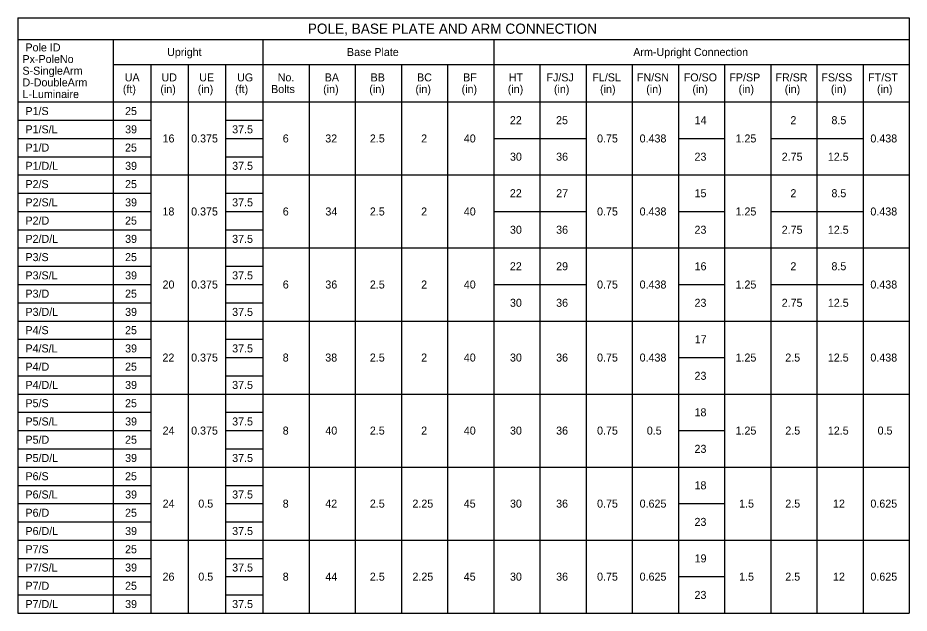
# Model space of a CAD drawing. Extents: x -1.3 to 14.1, y 0 to 9.3.
# Drawn here: x 6.35 to 14.14, y 4.14 to 9.34 of the extents above; entities that cross this region are included whole.
import ezdxf

# ---------------------------------------------------------------- set-up
doc = ezdxf.new("R2010")
doc.units = 0
for name, color, linetype in [('SumBoxBorder_dp', 7, 'Continuous'), ('SumBoxLines_dp', 7, 'Continuous'), ('TextLabel', 7, 'Continuous')]:
    doc.layers.add(name, color=color, linetype=linetype)

msp = doc.modelspace()

# ---------------------------------------------------------------- linework, layer by layer
at = {"layer": 'SumBoxBorder_dp'}
for p, q in [((6.345, 9.3443), (14.1396, 9.3443)), ((6.345, 9.3443), (6.345, 4.1392)), ((14.1396, 9.3443), (14.1396, 4.1392)), ((6.345, 9.1545), (14.1396, 9.1545)), ((6.345, 9.1545), (14.1396, 9.1545)), ((6.345, 4.1392), (14.1396, 4.1392))]:
    msp.add_line(p, q, dxfattribs=at)
at = {"layer": 'SumBoxLines_dp'}
for p, q in [((7.1796, 9.1545), (7.1796, 4.1392)), ((7.1796, 9.1545), (7.1796, 4.1392)), ((8.4887, 9.1545), (8.4887, 4.1392)), ((8.4887, 9.1545), (8.4887, 4.1392)), ((10.5069, 9.1545), (10.5069, 4.1392)), ((10.5069, 9.1545), (10.5069, 4.1392)), ((7.1796, 8.9363), (14.1396, 8.9363)), ((7.1796, 8.9363), (14.1396, 8.9363)), ((7.5069, 8.9363), (7.5069, 4.1392)), ((7.5069, 8.9363), (7.5069, 4.1392)), ((7.8341, 8.9363), (7.8341, 4.1392)), ((7.8341, 8.9363), (7.8341, 4.1392)), ((8.1614, 8.9363), (8.1614, 4.1392)), ((8.1614, 8.9363), (8.1614, 4.1392)), ((8.8923, 8.9363), (8.8923, 4.1392)), ((8.8923, 8.9363), (8.8923, 4.1392)), ((9.2959, 8.9363), (9.2959, 4.1392)), ((9.2959, 8.9363), (9.2959, 4.1392)), ((9.6996, 8.9363), (9.6996, 4.1392)), ((9.6996, 8.9363), (9.6996, 4.1392)), ((10.1032, 8.9363), (10.1032, 4.1392)), ((10.1032, 8.9363), (10.1032, 4.1392)), ((10.9105, 8.9363), (10.9105, 4.1392)), ((10.9105, 8.9363), (10.9105, 4.1392)), ((11.3141, 8.9363), (11.3141, 4.1392)), ((11.3141, 8.9363), (11.3141, 4.1392)), ((11.7178, 8.9363), (11.7178, 4.1392)), ((11.7178, 8.9363), (11.7178, 4.1392)), ((12.1214, 8.9363), (12.1214, 4.1392)), ((12.1214, 8.9363), (12.1214, 4.1392)), ((12.525, 8.9363), (12.525, 4.1392)), ((12.525, 8.9363), (12.525, 4.1392)), ((12.9287, 8.9363), (12.9287, 4.1392)), ((12.9287, 8.9363), (12.9287, 4.1392)), ((13.3323, 8.9363), (13.3323, 4.1392)), ((13.3323, 8.9363), (13.3323, 4.1392)), ((13.7359, 8.9363), (13.7359, 4.1392)), ((13.7359, 8.9363), (13.7359, 4.1392)), ((6.345, 8.609), (14.1396, 8.609)), ((6.345, 8.609), (14.1396, 8.609)), ((6.345, 8.4494), (7.5069, 8.4494)), ((6.345, 8.4494), (7.5069, 8.4494)), ((8.1614, 8.4494), (8.4887, 8.4494)), ((8.1614, 8.4494), (8.4887, 8.4494)), ((6.345, 8.2897), (7.5069, 8.2897)), ((6.345, 8.2897), (7.5069, 8.2897)), ((8.1614, 8.2897), (8.4887, 8.2897)), ((8.1614, 8.2897), (8.4887, 8.2897)), ((10.5069, 8.2897), (11.3141, 8.2897)), ((10.5069, 8.2897), (11.3141, 8.2897)), ((12.1214, 8.2897), (12.525, 8.2897)), ((12.1214, 8.2897), (12.525, 8.2897)), ((12.9287, 8.2897), (13.7359, 8.2897)), ((12.9287, 8.2897), (13.7359, 8.2897)), ((6.345, 8.1301), (7.5069, 8.1301)), ((6.345, 8.1301), (7.5069, 8.1301)), ((8.1614, 8.1301), (8.4887, 8.1301)), ((8.1614, 8.1301), (8.4887, 8.1301)), ((6.345, 7.9705), (14.1396, 7.9705)), ((6.345, 7.9705), (14.1396, 7.9705)), ((6.345, 7.8108), (7.5069, 7.8108)), ((6.345, 7.8108), (7.5069, 7.8108)), ((8.1614, 7.8108), (8.4887, 7.8108)), ((8.1614, 7.8108), (8.4887, 7.8108)), ((6.345, 7.6512), (7.5069, 7.6512)), ((6.345, 7.6512), (7.5069, 7.6512)), ((8.1614, 7.6512), (8.4887, 7.6512)), ((8.1614, 7.6512), (8.4887, 7.6512)), ((10.5069, 7.6512), (11.3141, 7.6512)), ((10.5069, 7.6512), (11.3141, 7.6512)), ((12.1214, 7.6512), (12.525, 7.6512)), ((12.1214, 7.6512), (12.525, 7.6512)), ((12.9287, 7.6512), (13.7359, 7.6512)), ((12.9287, 7.6512), (13.7359, 7.6512)), ((6.345, 7.4915), (7.5069, 7.4915)), ((6.345, 7.4915), (7.5069, 7.4915)), ((8.1614, 7.4915), (8.4887, 7.4915)), ((8.1614, 7.4915), (8.4887, 7.4915)), ((6.345, 7.3319), (14.1396, 7.3319)), ((6.345, 7.3319), (14.1396, 7.3319)), ((6.345, 7.1723), (7.5069, 7.1723)), ((6.345, 7.1723), (7.5069, 7.1723)), ((8.1614, 7.1723), (8.4887, 7.1723)), ((8.1614, 7.1723), (8.4887, 7.1723)), ((6.345, 7.0126), (7.5069, 7.0126)), ((6.345, 7.0126), (7.5069, 7.0126)), ((8.1614, 7.0126), (8.4887, 7.0126)), ((8.1614, 7.0126), (8.4887, 7.0126)), ((10.5069, 7.0126), (11.3141, 7.0126)), ((10.5069, 7.0126), (11.3141, 7.0126)), ((12.1214, 7.0126), (12.525, 7.0126)), ((12.1214, 7.0126), (12.525, 7.0126)), ((12.9287, 7.0126), (13.7359, 7.0126)), ((12.9287, 7.0126), (13.7359, 7.0126)), ((6.345, 6.853), (7.5069, 6.853)), ((6.345, 6.853), (7.5069, 6.853)), ((8.1614, 6.853), (8.4887, 6.853)), ((8.1614, 6.853), (8.4887, 6.853)), ((6.345, 6.6934), (14.1396, 6.6934)), ((6.345, 6.6934), (14.1396, 6.6934)), ((6.345, 6.5337), (7.5069, 6.5337)), ((6.345, 6.5337), (7.5069, 6.5337)), ((8.1614, 6.5337), (8.4887, 6.5337)), ((8.1614, 6.5337), (8.4887, 6.5337)), ((6.345, 6.3741), (7.5069, 6.3741)), ((6.345, 6.3741), (7.5069, 6.3741)), ((8.1614, 6.3741), (8.4887, 6.3741)), ((8.1614, 6.3741), (8.4887, 6.3741)), ((12.1214, 6.3741), (12.525, 6.3741)), ((12.1214, 6.3741), (12.525, 6.3741)), ((6.345, 6.2145), (7.5069, 6.2145)), ((6.345, 6.2145), (7.5069, 6.2145)), ((8.1614, 6.2145), (8.4887, 6.2145)), ((8.1614, 6.2145), (8.4887, 6.2145)), ((6.345, 6.0548), (14.1396, 6.0548)), ((6.345, 6.0548), (14.1396, 6.0548)), ((6.345, 5.8952), (7.5069, 5.8952)), ((6.345, 5.8952), (7.5069, 5.8952)), ((8.1614, 5.8952), (8.4887, 5.8952)), ((8.1614, 5.8952), (8.4887, 5.8952)), ((6.345, 5.7355), (7.5069, 5.7355)), ((6.345, 5.7355), (7.5069, 5.7355)), ((8.1614, 5.7355), (8.4887, 5.7355)), ((8.1614, 5.7355), (8.4887, 5.7355)), ((12.1214, 5.7355), (12.525, 5.7355)), ((12.1214, 5.7355), (12.525, 5.7355)), ((6.345, 5.5759), (7.5069, 5.5759)), ((6.345, 5.5759), (7.5069, 5.5759)), ((8.1614, 5.5759), (8.4887, 5.5759)), ((8.1614, 5.5759), (8.4887, 5.5759)), ((6.345, 5.4163), (14.1396, 5.4163)), ((6.345, 5.4163), (14.1396, 5.4163)), ((6.345, 5.2566), (7.5069, 5.2566)), ((6.345, 5.2566), (7.5069, 5.2566)), ((8.1614, 5.2566), (8.4887, 5.2566)), ((8.1614, 5.2566), (8.4887, 5.2566)), ((6.345, 5.097), (7.5069, 5.097)), ((6.345, 5.097), (7.5069, 5.097)), ((8.1614, 5.097), (8.4887, 5.097)), ((8.1614, 5.097), (8.4887, 5.097)), ((12.1214, 5.097), (12.525, 5.097)), ((12.1214, 5.097), (12.525, 5.097)), ((6.345, 4.9374), (7.5069, 4.9374)), ((6.345, 4.9374), (7.5069, 4.9374)), ((8.1614, 4.9374), (8.4887, 4.9374)), ((8.1614, 4.9374), (8.4887, 4.9374)), ((6.345, 4.7777), (14.1396, 4.7777)), ((6.345, 4.7777), (14.1396, 4.7777)), ((6.345, 4.6181), (7.5069, 4.6181)), ((6.345, 4.6181), (7.5069, 4.6181)), ((8.1614, 4.6181), (8.4887, 4.6181)), ((8.1614, 4.6181), (8.4887, 4.6181)), ((6.345, 4.4585), (7.5069, 4.4585)), ((6.345, 4.4585), (7.5069, 4.4585)), ((8.1614, 4.4585), (8.4887, 4.4585)), ((8.1614, 4.4585), (8.4887, 4.4585)), ((12.1214, 4.4585), (12.525, 4.4585)), ((12.1214, 4.4585), (12.525, 4.4585)), ((6.345, 4.2988), (7.5069, 4.2988)), ((6.345, 4.2988), (7.5069, 4.2988)), ((8.1614, 4.2988), (8.4887, 4.2988)), ((8.1614, 4.2988), (8.4887, 4.2988))]:
    msp.add_line(p, q, dxfattribs=at)

# ---------------------------------------------------------------- texts
at = {"layer": 'TextLabel'}
for s, height, p in [('POLE, BASE PLATE AND ARM CONNECTION', 0.089091, (8.8806, 9.2048)), ('  Pole ID', 0.07, (6.3596, 9.0507)), ('Upright', 0.07, (7.6503, 9.0104)), ('Base Plate', 0.07, (9.2231, 9.0104)), ('Arm-Upright Connection', 0.07, (11.727, 9.0104)), (' Px-PoleNo', 0.07, (6.3596, 8.9487)), (' S-SingleArm', 0.07, (6.3596, 8.8467)), (' D-DoubleArm', 0.07, (6.3596, 8.7447)), ('UA', 0.07, (7.2796, 8.7886)), ('UD', 0.07, (7.6015, 8.7886)), ('UE', 0.07, (7.9316, 8.7886)), ('UG', 0.07, (8.2625, 8.7886)), ('No.', 0.07, (8.6175, 8.7886)), ('BA', 0.07, (9.0287, 8.7886)), ('BB', 0.07, (9.43, 8.7886)), ('BC', 0.07, (9.8362, 8.7886)), ('BF', 0.07, (10.2391, 8.7886)), ('HT', 0.07, (10.638, 8.7886)), ('FJ/SJ', 0.07, (10.9673, 8.7886)), ('FL/SL', 0.07, (11.369, 8.7886)), ('FN/SN', 0.07, (11.7588, 8.7886)), ('FO/SO', 0.07, (12.1681, 8.7886)), ('FP/SP', 0.07, (12.5668, 8.7886)), ('FR/SR', 0.07, (12.9703, 8.7886)), ('FS/SS', 0.07, (13.3719, 8.7886)), ('FT/ST', 0.07, (13.7811, 8.7886)), ('(ft)', 0.07, (7.2633, 8.6866)), ('(in)', 0.07, (7.5913, 8.6866)), ('(in)', 0.07, (7.9186, 8.6866)), ('(ft)', 0.07, (8.2451, 8.6866)), ('Bolts', 0.07, (8.5599, 8.6866)), ('(in)', 0.07, (9.015, 8.6866)), ('(in)', 0.07, (9.4186, 8.6866)), ('(in)', 0.07, (9.8223, 8.6866)), ('(in)', 0.07, (10.2259, 8.6866)), ('(in)', 0.07, (10.6295, 8.6866)), ('(in)', 0.07, (11.0332, 8.6866)), ('(in)', 0.07, (11.4368, 8.6866)), ('(in)', 0.07, (11.8404, 8.6866)), ('(in)', 0.07, (12.2441, 8.6866)), ('(in)', 0.07, (12.6477, 8.6866)), ('(in)', 0.07, (13.0513, 8.6866)), ('(in)', 0.07, (13.455, 8.6866)), ('(in)', 0.07, (13.8586, 8.6866)), (' L-Luminaire', 0.07, (6.3596, 8.6427)), ('  P1/S', 0.07, (6.3596, 8.4942)), ('25', 0.07, (7.2827, 8.4942)), ('22', 0.07, (10.6479, 8.4144)), ('25', 0.07, (11.0518, 8.4144)), ('14', 0.07, (12.2638, 8.4144)), ('2', 0.07, (13.1011, 8.4144)), ('8.5', 0.07, (13.4599, 8.4144)), ('  P1/S/L', 0.07, (6.3596, 8.3345)), ('39', 0.07, (7.2832, 8.3345)), ('37.5', 0.07, (8.2193, 8.3345)), ('16', 0.07, (7.6105, 8.2547)), ('0.375', 0.07, (7.8606, 8.2547)), ('6', 0.07, (8.6619, 8.2547)), ('32', 0.07, (9.0334, 8.2547)), ('2.5', 0.07, (9.4235, 8.2547)), ('2', 0.07, (9.8721, 8.2547)), ('40', 0.07, (10.2451, 8.2547)), ('0.75', 0.07, (11.4102, 8.2547)), ('0.438', 0.07, (11.7824, 8.2547)), ('1.25', 0.07, (12.6212, 8.2547)), ('0.438', 0.07, (13.8005, 8.2547)), ('  P1/D', 0.07, (6.3596, 8.1749)), ('25', 0.07, (7.2827, 8.1749)), ('30', 0.07, (10.6488, 8.0951)), ('36', 0.07, (11.0523, 8.0951)), ('23', 0.07, (12.2624, 8.0951)), ('2.75', 0.07, (13.0248, 8.0951)), ('12.5', 0.07, (13.4284, 8.0951)), ('  P1/D/L', 0.07, (6.3596, 8.0153)), ('39', 0.07, (7.2832, 8.0153)), ('37.5', 0.07, (8.2193, 8.0153)), ('  P2/S', 0.07, (6.3596, 7.8556)), ('25', 0.07, (7.2827, 7.8556)), ('22', 0.07, (10.6479, 7.7758)), ('27', 0.07, (11.0531, 7.7758)), ('15', 0.07, (12.2627, 7.7758)), ('2', 0.07, (13.1011, 7.7758)), ('8.5', 0.07, (13.4599, 7.7758)), ('  P2/S/L', 0.07, (6.3596, 7.696)), ('39', 0.07, (7.2832, 7.696)), ('37.5', 0.07, (8.2193, 7.696)), ('18', 0.07, (7.6099, 7.6162)), ('0.375', 0.07, (7.8606, 7.6162)), ('6', 0.07, (8.6619, 7.6162)), ('34', 0.07, (9.0347, 7.6162)), ('2.5', 0.07, (9.4235, 7.6162)), ('2', 0.07, (9.8721, 7.6162)), ('40', 0.07, (10.2451, 7.6162)), ('0.75', 0.07, (11.4102, 7.6162)), ('0.438', 0.07, (11.7824, 7.6162)), ('1.25', 0.07, (12.6212, 7.6162)), ('0.438', 0.07, (13.8005, 7.6162)), ('  P2/D', 0.07, (6.3596, 7.5364)), ('25', 0.07, (7.2827, 7.5364)), ('30', 0.07, (10.6488, 7.4565)), ('36', 0.07, (11.0523, 7.4565)), ('23', 0.07, (12.2624, 7.4565)), ('2.75', 0.07, (13.0248, 7.4565)), ('12.5', 0.07, (13.4284, 7.4565)), ('  P2/D/L', 0.07, (6.3596, 7.3767)), ('39', 0.07, (7.2832, 7.3767)), ('37.5', 0.07, (8.2193, 7.3767)), ('  P3/S', 0.07, (6.3596, 7.2171)), ('25', 0.07, (7.2827, 7.2171)), ('22', 0.07, (10.6479, 7.1373)), ('29', 0.07, (11.0523, 7.1373)), ('16', 0.07, (12.2632, 7.1373)), ('2', 0.07, (13.1011, 7.1373)), ('8.5', 0.07, (13.4599, 7.1373)), ('  P3/S/L', 0.07, (6.3596, 7.0575)), ('39', 0.07, (7.2832, 7.0575)), ('37.5', 0.07, (8.2193, 7.0575)), ('20', 0.07, (7.6106, 6.9776)), ('0.375', 0.07, (7.8606, 6.9776)), ('6', 0.07, (8.6619, 6.9776)), ('36', 0.07, (9.0341, 6.9776)), ('2.5', 0.07, (9.4235, 6.9776)), ('2', 0.07, (9.8721, 6.9776)), ('40', 0.07, (10.2451, 6.9776)), ('0.75', 0.07, (11.4102, 6.9776)), ('0.438', 0.07, (11.7824, 6.9776)), ('1.25', 0.07, (12.6212, 6.9776)), ('0.438', 0.07, (13.8005, 6.9776)), ('  P3/D', 0.07, (6.3596, 6.8978)), ('25', 0.07, (7.2827, 6.8978)), ('30', 0.07, (10.6488, 6.818)), ('36', 0.07, (11.0523, 6.818)), ('23', 0.07, (12.2624, 6.818)), ('2.75', 0.07, (13.0248, 6.818)), ('12.5', 0.07, (13.4284, 6.818)), ('  P3/D/L', 0.07, (6.3596, 6.7382)), ('39', 0.07, (7.2832, 6.7382)), ('37.5', 0.07, (8.2193, 6.7382)), ('  P4/S', 0.07, (6.3596, 6.5785)), ('25', 0.07, (7.2827, 6.5785)), ('17', 0.07, (12.264, 6.4987)), ('  P4/S/L', 0.07, (6.3596, 6.4189)), ('39', 0.07, (7.2832, 6.4189)), ('37.5', 0.07, (8.2193, 6.4189)), ('22', 0.07, (7.6097, 6.3391)), ('0.375', 0.07, (7.8606, 6.3391)), ('8', 0.07, (8.6613, 6.3391)), ('38', 0.07, (9.0336, 6.3391)), ('2.5', 0.07, (9.4235, 6.3391)), ('2', 0.07, (9.8721, 6.3391)), ('40', 0.07, (10.2451, 6.3391)), ('30', 0.07, (10.6488, 6.3391)), ('36', 0.07, (11.0523, 6.3391)), ('0.75', 0.07, (11.4102, 6.3391)), ('0.438', 0.07, (11.7824, 6.3391)), ('1.25', 0.07, (12.6212, 6.3391)), ('2.5', 0.07, (13.0562, 6.3391)), ('12.5', 0.07, (13.4284, 6.3391)), ('0.438', 0.07, (13.8005, 6.3391)), ('  P4/D', 0.07, (6.3596, 6.2593)), ('25', 0.07, (7.2827, 6.2593)), ('23', 0.07, (12.2624, 6.1795)), ('  P4/D/L', 0.07, (6.3596, 6.0996)), ('39', 0.07, (7.2832, 6.0996)), ('37.5', 0.07, (8.2193, 6.0996)), ('  P5/S', 0.07, (6.3596, 5.94)), ('25', 0.07, (7.2827, 5.94)), ('18', 0.07, (12.2626, 5.8602)), ('  P5/S/L', 0.07, (6.3596, 5.7804)), ('39', 0.07, (7.2832, 5.7804)), ('37.5', 0.07, (8.2193, 5.7804)), ('24', 0.07, (7.6111, 5.7005)), ('0.375', 0.07, (7.8606, 5.7005)), ('8', 0.07, (8.6613, 5.7005)), ('40', 0.07, (9.0342, 5.7005)), ('2.5', 0.07, (9.4235, 5.7005)), ('2', 0.07, (9.8721, 5.7005)), ('40', 0.07, (10.2451, 5.7005)), ('30', 0.07, (10.6488, 5.7005)), ('36', 0.07, (11.0523, 5.7005)), ('0.75', 0.07, (11.4102, 5.7005)), ('0.5', 0.07, (11.8453, 5.7005)), ('1.25', 0.07, (12.6212, 5.7005)), ('2.5', 0.07, (13.0562, 5.7005)), ('12.5', 0.07, (13.4284, 5.7005)), ('0.5', 0.07, (13.8635, 5.7005)), ('  P5/D', 0.07, (6.3596, 5.6207)), ('25', 0.07, (7.2827, 5.6207)), ('  P5/D/L', 0.07, (6.3596, 5.4611)), ('23', 0.07, (12.2624, 5.5409)), ('39', 0.07, (7.2832, 5.4611)), ('37.5', 0.07, (8.2193, 5.4611)), ('  P6/S', 0.07, (6.3596, 5.3015)), ('25', 0.07, (7.2827, 5.3015)), ('18', 0.07, (12.2626, 5.2216)), ('  P6/S/L', 0.07, (6.3596, 5.1418)), ('39', 0.07, (7.2832, 5.1418)), ('37.5', 0.07, (8.2193, 5.1418)), ('24', 0.07, (7.6111, 5.062)), ('0.5', 0.07, (7.9235, 5.062)), ('8', 0.07, (8.6613, 5.062)), ('42', 0.07, (9.0334, 5.062)), ('2.5', 0.07, (9.4235, 5.062)), ('2.25', 0.07, (9.7957, 5.062)), ('45', 0.07, (10.2445, 5.062)), ('30', 0.07, (10.6488, 5.062)), ('36', 0.07, (11.0523, 5.062)), ('0.75', 0.07, (11.4102, 5.062)), ('0.625', 0.07, (11.7825, 5.062)), ('1.5', 0.07, (12.6526, 5.062)), ('2.5', 0.07, (13.0562, 5.062)), ('12', 0.07, (13.4734, 5.062)), ('0.625', 0.07, (13.8006, 5.062)), ('  P6/D', 0.07, (6.3596, 4.9822)), ('25', 0.07, (7.2827, 4.9822)), ('23', 0.07, (12.2624, 4.9024)), ('  P6/D/L', 0.07, (6.3596, 4.8225)), ('39', 0.07, (7.2832, 4.8225)), ('37.5', 0.07, (8.2193, 4.8225)), ('  P7/S', 0.07, (6.3596, 4.6629)), ('25', 0.07, (7.2827, 4.6629)), ('19', 0.07, (12.2632, 4.5831)), ('  P7/S/L', 0.07, (6.3596, 4.5033)), ('39', 0.07, (7.2832, 4.5033)), ('37.5', 0.07, (8.2193, 4.5033)), ('26', 0.07, (7.6105, 4.4235)), ('0.5', 0.07, (7.9235, 4.4235)), ('8', 0.07, (8.6613, 4.4235)), ('44', 0.07, (9.0347, 4.4235)), ('2.5', 0.07, (9.4235, 4.4235)), ('2.25', 0.07, (9.7957, 4.4235)), ('45', 0.07, (10.2445, 4.4235)), ('30', 0.07, (10.6488, 4.4235)), ('36', 0.07, (11.0523, 4.4235)), ('0.75', 0.07, (11.4102, 4.4235)), ('0.625', 0.07, (11.7825, 4.4235)), ('1.5', 0.07, (12.6526, 4.4235)), ('2.5', 0.07, (13.0562, 4.4235)), ('12', 0.07, (13.4734, 4.4235)), ('0.625', 0.07, (13.8006, 4.4235)), ('  P7/D', 0.07, (6.3596, 4.3436)), ('25', 0.07, (7.2827, 4.3436)), ('23', 0.07, (12.2624, 4.2638)), ('  P7/D/L', 0.07, (6.3596, 4.184)), ('39', 0.07, (7.2832, 4.184)), ('37.5', 0.07, (8.2193, 4.184))]:
    msp.add_text(s, height=height, dxfattribs=at).set_placement(p)

doc.saveas('drawing.dxf')
